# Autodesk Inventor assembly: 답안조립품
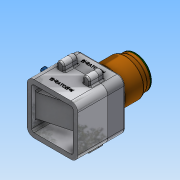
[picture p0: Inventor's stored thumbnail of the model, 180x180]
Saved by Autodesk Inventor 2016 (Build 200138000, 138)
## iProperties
Created: 2018-01
Part Number: 답안조립품
Material: 일반
Document SubType Name: Assembly
Designer: Administrator
Author: Administrator
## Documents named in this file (9)
- C:\Users\Administrator\Desktop\480108V1033\답안조립품.iam
- C:\Users\Administrator\Desktop\480108V1033\핸들축.ipt
- C:\Users\Administrator\Desktop\480108V1033\본체.ipt
- C:\Users\Administrator\Desktop\480108V1033\본체커버.ipt
- C:\Users\Administrator\Desktop\480108V1033\볼트 M3x12.ipt
- C:\Users\Administrator\Desktop\480108V1033\볼트 M4x12.ipt
- C:\Users\Administrator\Desktop\480108V1033\용기.ipt
- C:\Users\Administrator\Desktop\480108V1033\용기캡.ipt
- C:\Users\Administrator\Desktop\480108V1033\핸들.ipt
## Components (2 placed, 2 different names)
1. 핸들축:2 — 각도:1
2. 핸들:2 — 각도:1
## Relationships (1: Angle 1)
- 각도:1 [Angle]: 핸들축:2 ↔ 핸들:2
